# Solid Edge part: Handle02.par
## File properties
Title: Handle
Subject: Robinet tournant
Author: P.BAILLY
Keywords: Sous-traité
Comments: Handle
Template: normal.par
Last saved by: ptcarter
Revision: 64
Application: Solid Edge
Category: Robinet
Manager: BU Mécanique
Company: Intergraph France
Quantité: 1
Accuracy: 0.99
File Size: 0
Number of Sheets: 0
Number of Objects: 0
Document Number: Handle
Revision: A
Project Name: Robinet tournant
Material: Z 10 CNT 18
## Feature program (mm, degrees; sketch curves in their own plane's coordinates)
sketch for "unnamed Protrusion 1" plane through (0, 0, 0) normal (1, 0, 0) x-axis (0, 1, 0)
  line (-43.2367, 0) -> (36.7633, 0)
  line (36.7633, 0) -> (57.9765, 21.2132)
  line (57.9765, 21.2132) -> (107.9765, 21.2132)
  line (107.9765, 26.2132) -> (107.9765, 21.2132)
  line (55.9054, 26.2132) -> (107.9765, 26.2132)
  line (34.6922, 5) -> (55.9054, 26.2132)
  line (-43.2367, 5) -> (34.6922, 5)
  line (-43.2367, 5) -> (-43.2367, 0)
extrude "unnamed Protrusion 1" add finite 100 symmetric
fillet "unnamed Round 1"
fillet "unnamed Round 2"
sketch for "unnamed Cutout 1" plane through (0, 0, 0) normal (0, 0, 1) x-axis (1, 0, 0)
  arc centre (0, 0) radius 32.2843 from (-22.8284, -22.8284) to (22.8284, -22.8284) ccw
  arc centre (20, -20) radius 4 from (22.8284, -22.8284) to (17.1716, -17.1716) ccw
  arc centre (0, 0) radius 24.2843 from (-17.1716, -17.1716) to (17.1716, -17.1716) ccw
  arc centre (-20, -20) radius 4 from (-22.8284, -22.8284) to (-17.1716, -17.1716) cw
extrude "unnamed Cutout 1" cut through along +normal
sketch for "unnamed Protrusion 2" plane through (0, 0, 0) normal (0, 0, 1) x-axis (1, 0, 0)
  line (50, -43.2367) -> (50, -63.2367)
  line (-50, -43.2367) -> (50, -43.2367)
  line (-50, -43.2367) -> (-50, -63.2367)
  line (-50, -63.2367) -> (50, -63.2367)
extrude "unnamed Protrusion 2" add finite 5 along +normal
sketch for "unnamed Cutout 2" plane through (0, 0, 0) normal (0, 0, 1) x-axis (1, 0, 0)
  arc centre (0, 0) radius 36.2843 from (19.3442, -30.6977) to (-20.267, -30.0964) cw
  arc centre (-11.7791, -17.4919) radius 15.1961 from (-25, -10) to (-20.267, -30.0964) ccw
  line (-25, -10) -> (-8, 20)
  line (-8, 99.9765) -> (-8, 20)
  arc centre (0, 99.9765) radius 8 from (-8, 99.9765) to (8, 99.9765) cw
  line (8, 99.9765) -> (8, 20)
  line (8, 20) -> (24.691, -9.4283)
  arc centre (10.8781, -17.2627) radius 15.88 from (24.691, -9.4283) to (19.3442, -30.6977) cw
extrude "unnamed Cutout 2" cut through along +normal
sketch for "unnamed Cutout 3" plane through (0, 0, 0) normal (0, 0, 1) x-axis (1, 0, 0)
  line (-4, -6.3443) -> (-4, 6.3443)
  arc centre (0, 0) radius 7.5 from (-4, 6.3443) to (4, 6.3443) cw
  line (4, -6.3443) -> (4, 6.3443)
  arc centre (0, 0) radius 7.5 from (4, -6.3443) to (-4, -6.3443) cw
extrude "unnamed Cutout 3" cut through along +normal
fillet "unnamed Round 3"
sketch for "unnamed Cutout 4" plane through (-0.1085, -4.4382, 5) normal (0, 0, 1) x-axis (0, 1, 0)
extrude "unnamed Cutout 4" cut through along +normal
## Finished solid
Body 1: solid body, 32 faces, 92 edges, 60 vertices.
  Faces by surface: cylinder 18, plane 14
  Edges by curve: line 56, circle 34, intersection 2
Bounding box of the edges (mm): 53.733 x 144.261 x 26.213, from (-26.9752, -36.2843, 0) to (26.7581, 107.9765, 26.2132).
Cylindrical faces by radius (mm): R4 x2, R5 x2, R7.5 x2, R8 x1, R15.1961 x1, R15.88 x1, R20 x4, R24.2843 x1, R25 x2, R32.2843 x1, R36.2843 x1
Planar faces by outward normal: +x 3, +z 2, -x 3, -z 2, oblique 4
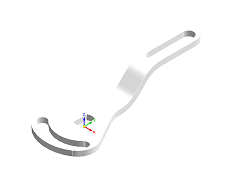
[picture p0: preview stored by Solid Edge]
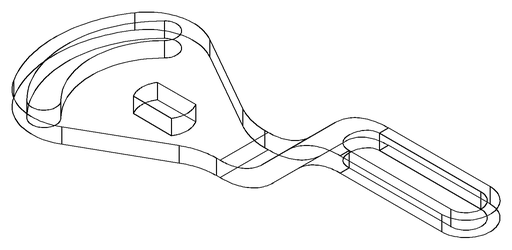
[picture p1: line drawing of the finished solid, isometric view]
